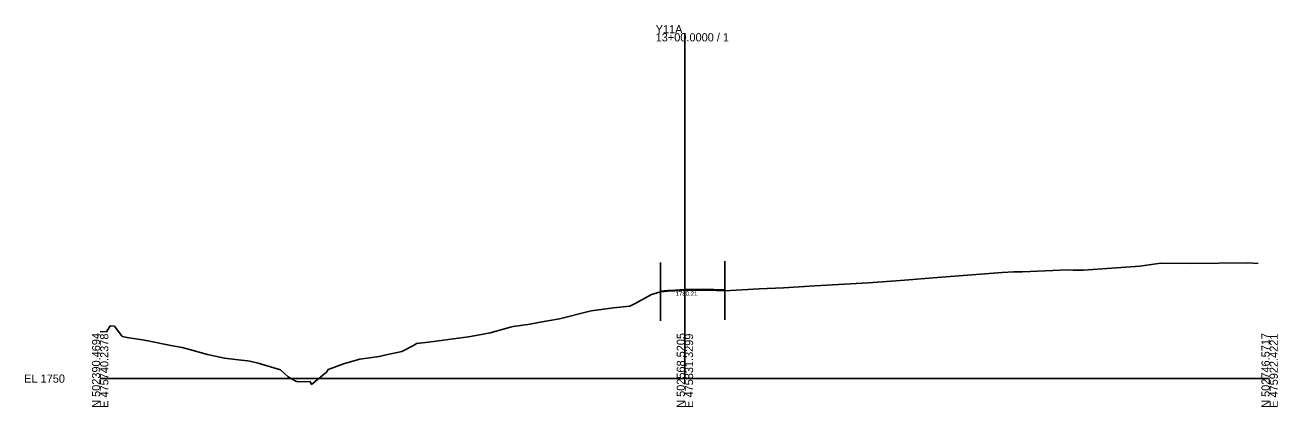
# Model space of a CAD drawing. Extents: x -26 to 403, y -10 to 5098.
# Drawn here: x -25.7 to 402.8, y 2990.3 to 3120.9 of the extents above; entities that cross this region are included whole.
import ezdxf

# ---------------------------------------------------------------- set-up
doc = ezdxf.new("R2010")
doc.units = 0
for name, color, linetype in [('Exist Cross Section Cell', 7, 'Continuous'), ('Exist XS Center Line Elevation Label', 7, 'Continuous'), ('Exist XS Ground Line', 7, 'Continuous'), ('Prop XS Finish Grade Pavement', 7, 'Continuous'), ('Scratch_Level_5', 7, 'Continuous')]:
    doc.layers.add(name, color=color, linetype=linetype)

msp = doc.modelspace()

# ---------------------------------------------------------------- linework, layer by layer
at = {"layer": 'Exist Cross Section Cell'}
for p, q in [((200, 3000), (200, 3118.15)), ((0, 3000), (200, 3000)), ((200, 3000), (400, 3000))]:
    msp.add_line(p, q, dxfattribs=at)
at = {"layer": 'Exist XS Ground Line'}
msp.add_lwpolyline([(0, 3016.1), (2.16, 3015.96), (3.44, 3018.01), (4.86, 3017.97), (7.57, 3014.43), (9.79, 3013.98), (14.44, 3013.22), (16.82, 3012.79), (24.18, 3011.34), (28.05, 3010.64), (29.3, 3010.3), (31.75, 3009.66), (36.74, 3008.2), (39.29, 3007.66), (42.51, 3006.94), (48.21, 3006.34), (50.52, 3006.04), (51.6, 3005.85), (54.04, 3005.26), (61.64, 3002.95), (64.35, 3000.61), (66.64, 2999.25), (67.51, 2998.86), (71.78, 2999.03), (72.29, 2998.03), (77.38, 3002.25), (78.01, 3003.11), (80.53, 3003.98), (83.22, 3005.08), (88.76, 3006.68), (95.46, 3007.62), (96.85, 3007.85), (103.13, 3009.24), (107.44, 3011.46), (108.14, 3011.97), (112.35, 3012.5), (125.93, 3014.34), (129.17, 3014.89), (133.36, 3015.64), (140.4, 3017.65), (141.29, 3017.83), (147.02, 3018.57), (150.54, 3019.34), (157.12, 3020.47), (167.89, 3023.16), (175.56, 3024.18), (181.19, 3024.79), (183.16, 3025.85), (188.6, 3028.82), (190.55, 3029.38), (191.64, 3029.72), (194.21, 3029.91), (196.59, 3030.03), (198.28, 3030.12), (200, 3030.21), (200.45, 3030.23), (202.16, 3030.25), (204.76, 3030.24), (207.22, 3030.23), (209.87, 3030.21), (210.72, 3030.17), (213.6, 3030.07), (225.4, 3030.69), (233.69, 3031.05), (244.46, 3031.73), (262.71, 3032.78), (273.7, 3033.55), (287.71, 3034.71), (308.57, 3036.34), (312.5, 3036.48), (315.48, 3036.54), (331.01, 3037.21), (332.78, 3037.09), (336.39, 3037.06), (355.64, 3038.47), (362.8, 3039.53), (372.82, 3039.42), (392.56, 3039.61), (396.05, 3039.42)], dxfattribs=at)
at = {"layer": 'Prop XS Finish Grade Pavement'}
for p, q in [((191.61, 3029.97), (191.61, 3029.71)), ((213.7, 3030.33), (213.7, 3030.08))]:
    msp.add_line(p, q, dxfattribs=at)
msp.add_lwpolyline([(191.61, 3029.97), (194.2, 3030.16), (196.57, 3030.28), (198.26, 3030.37), (199.99, 3030.46), (200.44, 3030.48), (202.16, 3030.5), (204.76, 3030.49), (207.22, 3030.48), (209.88, 3030.46), (210.73, 3030.42), (213.59, 3030.33), (213.7, 3030.33)], dxfattribs=at)
at = {"layer": 'Scratch_Level_5'}
for p, q in [((191.61, 3039.71), (191.61, 3019.71)), ((213.7, 3040.12), (213.7, 3020.12))]:
    msp.add_line(p, q, dxfattribs=at)

# ---------------------------------------------------------------- texts
at = {"layer": 'Exist Cross Section Cell'}
for s, p in [('Y11A', (190, 3118.15)), ('13+00.0000 / 1', (190, 3115.35)), ('EL 1750', (-26, 2998.6))]:
    msp.add_text(s, height=2.8, dxfattribs=at).set_placement(p)
for s, p in [('N 502390.4694', (0, 2990)), ('E 475740.2378', (2.8, 2990)), ('N 502568.5205', (200, 2990)), ('E 475831.3299', (202.8, 2990)), ('N 502746.5717', (400, 2990)), ('E 475922.4221', (402.8, 2990))]:
    msp.add_text(s, height=2.8, rotation=90, dxfattribs=at).set_placement(p)
at = {"layer": 'Exist XS Center Line Elevation Label'}
msp.add_text('1780.21', height=1.5, dxfattribs=at).set_placement((196.81, 3028.32))

doc.saveas('drawing.dxf')
